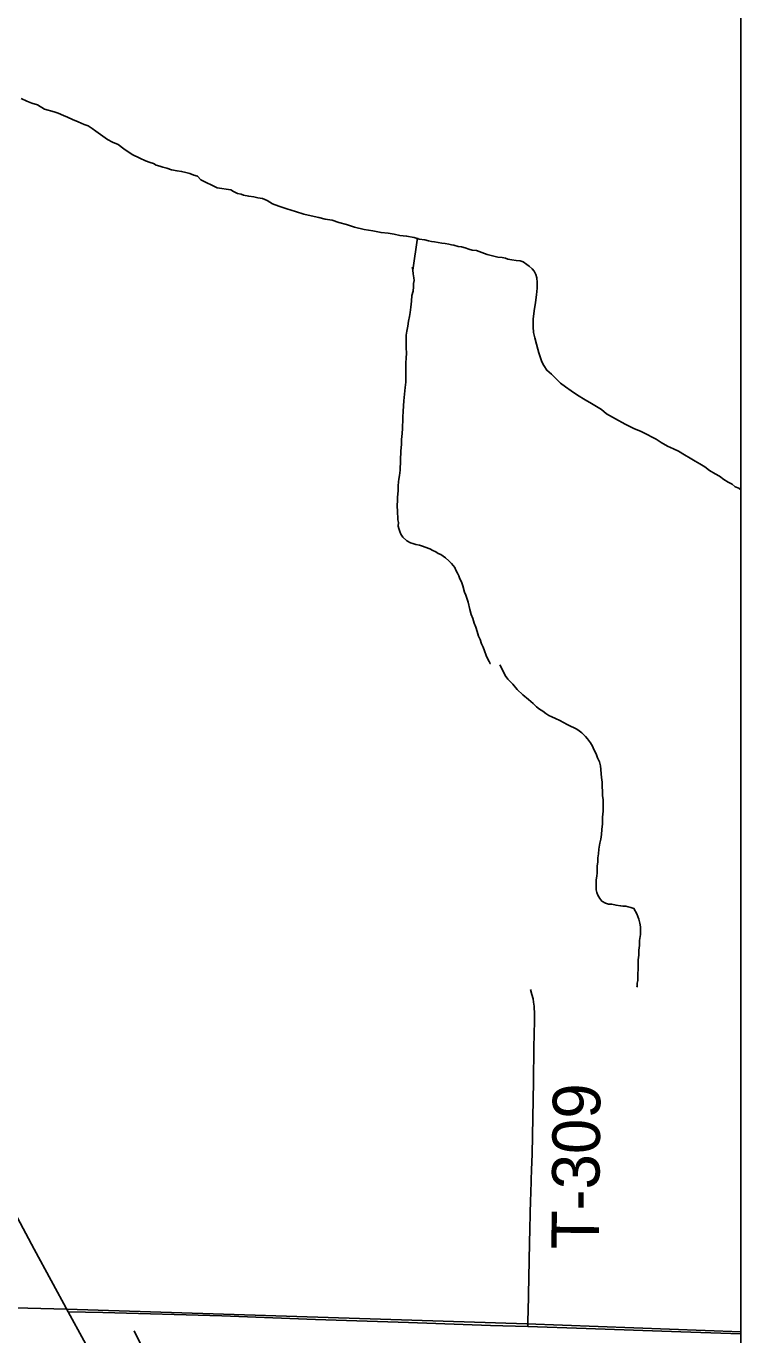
# Model space of a CAD drawing. Extents: x 1 to 1971, y -2 to 1107.
# Drawn here: x 1668.44 to 1672.2, y 1091.98 to 1098.86 of the extents above; entities that cross this region are included whole.
import ezdxf

# ---------------------------------------------------------------- set-up
doc = ezdxf.new("R2010")
doc.units = 0
for name, color, linetype in [('GM_X_Minor_River', 7, 'Continuous'), ('GM_X_Township', 7, 'Continuous'), ('GM_X_Township_Road', 7, 'Continuous'), ('GM_X_Township_Road_Text', 7, 'Continuous'), ('SH_Data', 7, 'Continuous'), ('SH_Text', 7, 'Continuous'), ('SN_P_Signs', 7, 'Continuous')]:
    doc.layers.add(name, color=color, linetype=linetype)

msp = doc.modelspace()

# ---------------------------------------------------------------- linework, layer by layer
at = {"layer": 'GM_X_Minor_River'}
for points in [[(1668.4177, 1098.4827), (1668.4471, 1098.4689), (1668.4738, 1098.4579), (1668.5032, 1098.4495), (1668.5405, 1098.4275), (1668.5914, 1098.4135), (1668.6128, 1098.4052), (1668.6395, 1098.3941), (1668.6609, 1098.3858), (1668.6875, 1098.372), (1668.7169, 1098.3609), (1668.749, 1098.3471), (1668.7704, 1098.3388), (1668.7917, 1098.3251), (1668.8103, 1098.3115), (1668.8715, 1098.2678), (1668.8982, 1098.2541), (1668.9276, 1098.2403), (1668.9569, 1098.2185), (1669.0021, 1098.1884), (1669.0422, 1098.1691), (1669.0715, 1098.1554), (1669.0956, 1098.147), (1669.1143, 1098.1414), (1669.1277, 1098.1332), (1669.1464, 1098.1276), (1669.1624, 1098.122), (1669.1838, 1098.1164), (1669.2079, 1098.108), (1669.2374, 1098.1023), (1669.2615, 1098.0993), (1669.2829, 1098.0937), (1669.3043, 1098.088), (1669.3257, 1098.0797), (1669.3444, 1098.0741), (1669.363, 1098.0551), (1669.4484, 1098.0138), (1669.5208, 1098.0021), (1669.5341, 1097.9939), (1669.5555, 1097.9829), (1669.5742, 1097.98), (1669.5876, 1097.9745), (1669.6144, 1097.9688), (1669.6412, 1097.9657), (1669.6626, 1097.9601), (1669.6867, 1097.9571), (1669.7108, 1097.9461), (1669.7401, 1097.9296), (1669.7722, 1097.9158), (1669.8149, 1097.9018), (1669.8604, 1097.8879), (1669.9032, 1097.8739), (1669.9434, 1097.8653), (1669.9836, 1097.8568), (1670.0157, 1097.8483), (1670.0532, 1097.8425), (1670.088, 1097.8313), (1670.1281, 1097.82), (1670.1709, 1097.8061), (1670.2218, 1097.7947), (1670.2674, 1097.7861), (1670.3102, 1097.7775), (1670.3478, 1097.7743), (1670.3799, 1097.7685), (1670.4094, 1097.7628), (1670.4443, 1097.7596), (1670.4845, 1097.7511), (1670.5112, 1097.7427), (1670.5407, 1097.7396), (1670.5595, 1097.734), (1670.5755, 1097.7311), (1670.5916, 1097.7282), (1670.6104, 1097.7253), (1670.6291, 1097.7224), (1670.6479, 1097.7195), (1670.6667, 1097.7165), (1670.6801, 1097.7137), (1670.6934, 1097.7108), (1670.7149, 1097.7052), (1670.7336, 1097.7023), (1670.7523, 1097.6967), (1670.7711, 1097.6911), (1670.7898, 1097.6855), (1670.8113, 1097.6825), (1670.8674, 1097.663), (1670.8968, 1097.6546), (1670.9236, 1097.6489), (1670.9478, 1097.6459), (1670.9639, 1097.643), (1670.9772, 1097.6375), (1670.9987, 1097.6345), (1671.0201, 1097.6315), (1671.0415, 1097.6286), (1671.0576, 1097.623), (1671.0762, 1097.6094), (1671.0895, 1097.6011), (1671.1055, 1097.5875), (1671.1161, 1097.574)], [(1670.502, 1097.7503), (1670.4769, 1097.5797), (1670.4744, 1097.5932), (1670.4769, 1097.5797), (1670.4794, 1097.561), (1670.4818, 1097.5395), (1670.4843, 1097.5261), (1670.4814, 1097.51), (1670.4812, 1097.4913), (1670.4782, 1097.4699), (1670.4726, 1097.4459), (1670.4695, 1097.4164), (1670.4664, 1097.3843), (1670.4634, 1097.3576), (1670.4604, 1097.3362), (1670.4548, 1097.3122), (1670.4517, 1097.2854), (1670.446, 1097.2587), (1670.4431, 1097.2373), (1670.4429, 1097.2212), (1670.4426, 1097.2025), (1670.4422, 1097.1704), (1670.4446, 1097.1435), (1670.4416, 1097.1168), (1670.4413, 1097.0927), (1670.4409, 1097.0632), (1670.4405, 1097.0365), (1670.4402, 1097.0123), (1670.44, 1096.9909), (1670.4369, 1096.9615), (1670.4338, 1096.9267), (1670.4307, 1096.8919), (1670.4273, 1096.8384), (1670.4242, 1096.8063), (1670.4239, 1096.7795), (1670.4237, 1096.7661), (1670.4235, 1096.7474), (1670.4204, 1096.7206), (1670.4173, 1096.6885), (1670.417, 1096.6617), (1670.4139, 1096.6296), (1670.4133, 1096.5787), (1670.41, 1096.5279), (1670.4069, 1096.4985), (1670.404, 1096.4798), (1670.4011, 1096.4664), (1670.4009, 1096.445), (1670.4005, 1096.4182), (1670.3974, 1096.3861), (1670.3971, 1096.362), (1670.3942, 1096.346), (1670.3964, 1096.3031), (1670.3988, 1096.2789), (1670.3986, 1096.2655), (1670.4011, 1096.2521), (1670.4009, 1096.2334), (1670.4034, 1096.2199), (1670.4086, 1096.2038), (1670.4138, 1096.1903), (1670.4243, 1096.1741), (1670.4455, 1096.1551), (1670.4642, 1096.1441), (1670.4776, 1096.1413), (1670.4936, 1096.1357), (1670.5124, 1096.1328), (1670.5285, 1096.1272), (1670.5418, 1096.1217), (1670.5659, 1096.1133), (1670.5819, 1096.1051), (1670.5979, 1096.0968), (1670.6112, 1096.0886), (1670.6246, 1096.0831), (1670.6485, 1096.0667), (1670.6671, 1096.0504), (1670.6804, 1096.0368), (1670.6989, 1096.0152), (1670.7041, 1096.0017), (1670.712, 1095.9855), (1670.7199, 1095.972), (1670.725, 1095.9559), (1670.7329, 1095.9397), (1670.7407, 1095.9182), (1670.7483, 1095.8859), (1670.7562, 1095.8697), (1670.7691, 1095.8321), (1670.7767, 1095.7945), (1670.7844, 1095.7676), (1670.7922, 1095.7461), (1670.8, 1095.7219), (1670.8078, 1095.7003), (1670.8155, 1095.6788), (1670.8233, 1095.6546), (1670.8311, 1095.6357), (1670.8389, 1095.6142), (1670.8467, 1095.5953), (1670.8545, 1095.5765), (1670.8623, 1095.5523), (1670.8701, 1095.5361), (1670.878, 1095.5199), (1670.8832, 1095.5091), (1670.8859, 1095.5091)], [(1671.1161, 1097.574), (1671.1239, 1097.5578), (1671.129, 1097.539), (1671.1314, 1097.5149), (1671.1311, 1097.4854), (1671.1279, 1097.4506), (1671.1221, 1097.4105), (1671.1161, 1097.3651), (1671.1102, 1097.3223), (1671.1097, 1097.2821), (1671.112, 1097.2526), (1671.1197, 1097.2231), (1671.1273, 1097.1908), (1671.1351, 1097.1639), (1671.1402, 1097.1451), (1671.1454, 1097.129), (1671.1505, 1097.1128), (1671.1557, 1097.0967), (1671.1662, 1097.0778), (1671.182, 1097.0535), (1671.2059, 1097.0317), (1671.2537, 1096.9856), (1671.2803, 1096.9665), (1671.3095, 1096.9447), (1671.3442, 1096.9228), (1671.3842, 1096.8981), (1671.4161, 1096.879), (1671.4428, 1096.8625), (1671.4695, 1096.8461), (1671.496, 1096.8243), (1671.544, 1096.7969), (1671.5947, 1096.7695), (1671.6401, 1096.7474), (1671.6775, 1096.7309), (1671.7095, 1096.7144), (1671.7362, 1096.7007), (1671.7575, 1096.6897), (1671.7842, 1096.6732), (1671.8162, 1096.6541), (1671.8482, 1096.6402), (1671.8749, 1096.6265), (1671.9069, 1096.6073), (1671.9362, 1096.5909), (1671.9629, 1096.5744), (1671.9869, 1096.5607), (1672.0135, 1096.5443), (1672.0375, 1096.5252), (1672.0668, 1096.5088), (1672.0908, 1096.4951), (1672.1121, 1096.4787), (1672.1361, 1096.465), (1672.1574, 1096.454), (1672.1734, 1096.4404), (1672.1921, 1096.4321), (1672.2022, 1096.4247)], [(1670.9354, 1095.5037), (1670.9574, 1095.4596), (1670.9627, 1095.4462), (1670.9761, 1095.4274), (1671.0027, 1095.4006), (1671.0268, 1095.3737), (1671.0561, 1095.3442), (1671.0855, 1095.32), (1671.1095, 1095.2986), (1671.1282, 1095.2824), (1671.1443, 1095.269), (1671.1603, 1095.2583), (1671.1763, 1095.2475), (1671.1924, 1095.2368), (1671.2084, 1095.2287), (1671.2271, 1095.2206), (1671.2512, 1095.2098), (1671.2699, 1095.1991), (1671.2886, 1095.1883), (1671.3073, 1095.1802), (1671.326, 1095.1721), (1671.3394, 1095.164), (1671.3527, 1095.156), (1671.3661, 1095.1452), (1671.3848, 1095.1264), (1671.3955, 1095.113), (1671.4115, 1095.0916), (1671.4221, 1095.0755), (1671.4301, 1095.0567), (1671.4408, 1095.0353), (1671.4487, 1095.0139), (1671.4594, 1094.9924), (1671.4647, 1094.971), (1671.4699, 1094.9094), (1671.4725, 1094.8854), (1671.4725, 1094.8586), (1671.4751, 1094.8399), (1671.475, 1094.8158), (1671.4777, 1094.7917), (1671.4776, 1094.7649), (1671.4775, 1094.7328), (1671.4748, 1094.7007), (1671.4747, 1094.666), (1671.4719, 1094.6365), (1671.4692, 1094.6098), (1671.4665, 1094.5857), (1671.4611, 1094.5643), (1671.4557, 1094.5323), (1671.4529, 1094.5082), (1671.4502, 1094.4868), (1671.4502, 1094.4654), (1671.4474, 1094.444), (1671.4474, 1094.4253), (1671.4473, 1094.4092), (1671.4446, 1094.3905), (1671.4419, 1094.3718), (1671.4419, 1094.353), (1671.4418, 1094.3397), (1671.4418, 1094.3183), (1671.4444, 1094.3049), (1671.4497, 1094.2915), (1671.4604, 1094.2727), (1671.4711, 1094.2593), (1671.4898, 1094.2485), (1671.5058, 1094.2431), (1671.5246, 1094.2431), (1671.546, 1094.2377), (1671.57, 1094.2349), (1671.5834, 1094.2322), (1671.5968, 1094.2321), (1671.6102, 1094.2294), (1671.6235, 1094.2267), (1671.6396, 1094.2213), (1671.6556, 1094.1918), (1671.6609, 1094.1784), (1671.6662, 1094.165), (1671.6715, 1094.1436), (1671.6741, 1094.1249), (1671.6741, 1094.1061), (1671.6741, 1094.0847), (1671.6686, 1094.0527), (1671.6686, 1094.0259), (1671.6658, 1094.0018), (1671.6658, 1093.9751), (1671.663, 1093.951), (1671.663, 1093.9242), (1671.6629, 1093.9002), (1671.6602, 1093.8788), (1671.6602, 1093.86), (1671.6601, 1093.8413), (1671.6574, 1093.8279), (1671.6574, 1093.8119), (1671.6547, 1093.8065)]]:
    msp.add_lwpolyline(points, dxfattribs=at)
at = {"layer": 'GM_X_Township'}
msp.add_lwpolyline([(1653.1763, 1092.4976), (1656.8592, 1092.4086), (1656.9549, 1092.4071), (1660.4424, 1092.2976), (1663.9517, 1092.2334), (1668.658, 1092.1116), (1671.0761, 1092.0354), (1672.2022, 1091.993)], dxfattribs=at)
at = {"layer": 'GM_X_Township_Road'}
for points in [[(1671.0823, 1092.0215), (1671.083, 1092.0573), (1671.0837, 1092.0982), (1671.0914, 1092.4601), (1671.0964, 1092.6878), (1671.0971, 1092.7185), (1671.0995, 1092.7929), (1671.1016, 1092.8454), (1671.1045, 1092.9285), (1671.1071, 1093.0248), (1671.1111, 1093.3095), (1671.1141, 1093.4891), (1671.1166, 1093.629), (1671.1172, 1093.6627), (1671.1147, 1093.7065), (1671.1128, 1093.7269), (1671.1096, 1093.7452), (1671.1037, 1093.7683), (1671.0964, 1093.794)], [(1668.6651, 1092.0989), (1668.8471, 1092.0955), (1669.4722, 1092.0774), (1669.9648, 1092.0577), (1670.4545, 1092.0423), (1670.8862, 1092.0269), (1671.0823, 1092.0215)], [(1671.0823, 1092.0215), (1671.3889, 1092.0101), (1671.887, 1091.9932), (1672.2022, 1091.982)]]:
    msp.add_lwpolyline(points, dxfattribs=at)
at = {"layer": 'SH_Data'}
msp.add_lwpolyline([(1653.1763, 1105.4005), (1672.2022, 1105.4005), (1672.2022, 1085.8005), (1653.1763, 1085.8005)], close=True, dxfattribs=at)
at = {"layer": 'SH_Text'}
msp.add_lwpolyline([(1667.0331, 1094.9821), (1667.036, 1094.9775), (1667.3422, 1094.472), (1667.5124, 1094.191), (1667.5577, 1094.1145), (1667.6338, 1093.9829), (1667.8558, 1093.5802), (1667.9723, 1093.3696), (1668.2781, 1092.8131), (1668.4867, 1092.4282), (1668.6651, 1092.0989), (1668.7474, 1091.947), (1669.0282, 1091.4269), (1669.2085, 1091.0948), (1669.731, 1090.1531)], dxfattribs=at)
at = {"layer": 'SN_P_Signs'}
msp.add_line((1669.0469, 1091.9264), (1669.0122, 1091.9985), dxfattribs=at)

# ---------------------------------------------------------------- texts
at = {"layer": 'GM_X_Township_Road_Text'}
msp.add_text('T-309', height=0.25, rotation=89.4372, dxfattribs=at).set_placement((1671.4556, 1092.4259))

doc.saveas('drawing.dxf')
